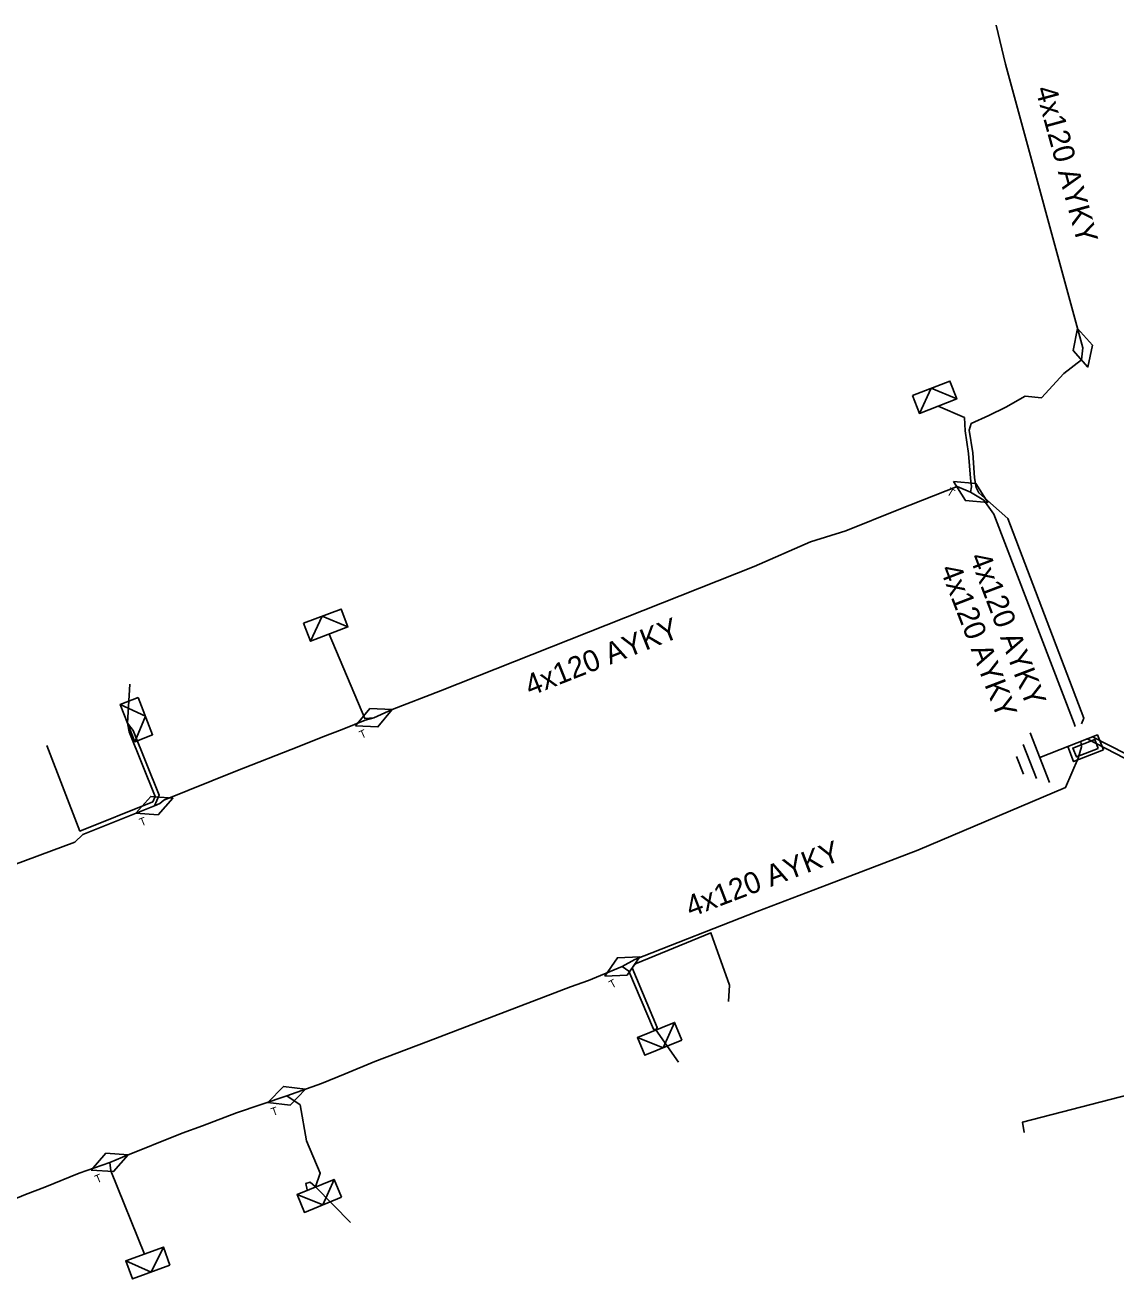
# Model space of a CAD drawing. Extents: x -540028 to -538776, y -1157064 to -1155670.
# Drawn here: x -539783.3 to -539732.2, y -1155842.1 to -1155783.4 of the extents above; entities that cross this region are included whole.
import ezdxf

# ---------------------------------------------------------------- set-up
doc = ezdxf.new("R2010")
doc.units = 0
for name, color, linetype in [('Vrstva 15', 7, 'Continuous'), ('Vrstva 19', 7, 'Continuous'), ('Vrstva 2', 7, 'Continuous'), ('Vrstva 28', 7, 'Continuous'), ('Vrstva 31', 7, 'Continuous'), ('Vrstva 5', 7, 'Continuous'), ('Vrstva 52', 7, 'Continuous'), ('Vrstva 59', 7, 'Continuous'), ('Vrstva 6', 7, 'Continuous')]:
    doc.layers.add(name, color=color, linetype=linetype)

# ---------------------------------------------------------------- blocks, each defined once
blk = doc.blocks.new('17')
at = {"layer": 'Vrstva 2'}
blk.add_lwpolyline([(-1.875, 0), (0, 0.9375), (1.875, 0), (0, -0.9375)], close=True, dxfattribs=at)
blk = doc.blocks.new('17.1')
at = {"layer": 'Vrstva 2'}
blk.add_lwpolyline([(-1.875, 0), (0, 0.9375), (1.875, 0), (0, -0.9375)], close=True, dxfattribs=at)
blk.add_text('T', height=0.75, dxfattribs=at).set_placement((-1.875, -1.35))
blk = doc.blocks.new('132')
at = {"layer": 'Vrstva 2'}
for points in [[(-1.5, 1.5), (1.5, 1.5), (1.5, 0), (-1.5, 0)], [(-1.1, 1.2), (1.1, 1.2), (1.1, 0.3), (-1.1, 0.3)]]:
    blk.add_lwpolyline(points, close=True, dxfattribs=at)
blk = doc.blocks.new('23')
at = {"layer": 'Vrstva 2'}
blk.add_lwpolyline([(1.875, -1.8), (-1.875, -1.8), (-1.875, 0), (1.875, 0)], close=True, dxfattribs=at)
blk.add_lwpolyline([(1.875, 0), (0, -1.8), (-1.875, 0)], dxfattribs=at)
blk = doc.blocks.new('11')
at = {"layer": 'Vrstva 2'}
for p, q in [((0, -4.3), (0, -1.3)), ((-2.5, -4.3), (2.5, -4.3)), ((-1.7, -5.3), (1.7, -5.3)), ((-0.9, -6.3), (0.9, -6.3))]:
    blk.add_line(p, q, dxfattribs=at)

msp = doc.modelspace()

# ---------------------------------------------------------------- linework, layer by layer
at = {"layer": 'Vrstva 5'}
for points in [[(-539737.801, -1155783.405), (-539737.37, -1155785.24), (-539733.75, -1155798.52)], [(-539733.804, -1155816.14), (-539733.7, -1155815.87), (-539737.26, -1155806.52), (-539738.61, -1155805.32), (-539738.746, -1155805.073), (-539738.811, -1155804.609), (-539738.901, -1155803.449), (-539739.061, -1155802.375), (-539738.97, -1155802.07), (-539738.14, -1155801.69), (-539737.35, -1155801.31), (-539736.447, -1155800.787), (-539735.68, -1155800.86), (-539734.63, -1155799.72), (-539733.81, -1155799.08), (-539733.75, -1155798.52)], [(-539734.097, -1155816.258), (-539734.15, -1155816.12), (-539737.92, -1155806.31), (-539738.38, -1155805.66), (-539739, -1155805.28), (-539739.63, -1155805.02), (-539742.36, -1155806.1), (-539744.85, -1155807.09), (-539746.49, -1155807.61), (-539749.14, -1155808.77), (-539763.83, -1155814.59), (-539766.08, -1155815.47), (-539766.94, -1155815.85), (-539767.35, -1155815.96), (-539768.42, -1155816.4), (-539769.33, -1155816.74), (-539770.45, -1155817.19), (-539773.41, -1155818.36), (-539776.78, -1155819.71), (-539776.957, -1155819.865), (-539777.218, -1155819.97)], [(-539777.218, -1155819.97), (-539776.998, -1155819.48), (-539778.217, -1155816.443), (-539778.48, -1155816.1)], [(-539733.834, -1155816.96), (-539733.81, -1155817.21), (-539733.96, -1155817.75), (-539734.55, -1155819.12), (-539741.47, -1155822.06), (-539745.72, -1155823.67), (-539749, -1155824.92), (-539754.726, -1155827.177), (-539755.31, -1155827.5)], [(-539733.288, -1155816.745), (-539731.73, -1155817.543)], [(-539777.218, -1155819.97), (-539780.574, -1155821.321), (-539780.94, -1155821.68), (-539784.34, -1155822.95), (-539784.6, -1155822.83), (-539785, -1155822.93), (-539786.12, -1155823.37), (-539788.17, -1155824.19), (-539789.28, -1155824.62), (-539791.3, -1155825.48), (-539791.66, -1155825.62), (-539792, -1155825.78), (-539794.27, -1155826.66), (-539797.23, -1155827.88), (-539797.924, -1155828.259)], [(-539785.64, -1155839.16), (-539783.26, -1155838.19), (-539782.35, -1155837.84), (-539780.74, -1155837.18), (-539779.31, -1155836.68), (-539778.71, -1155836.43), (-539775.92, -1155835.31), (-539774.97, -1155834.96), (-539773.38, -1155834.35), (-539771.025, -1155833.562), (-539769.39, -1155832.98), (-539768.28, -1155832.53), (-539766.9, -1155831.95), (-539764.38, -1155831), (-539757.73, -1155828.46), (-539756.89, -1155828.16), (-539755.31, -1155827.5)], [(-539755.31, -1155827.5), (-539754.996, -1155827.728), (-539753.856, -1155830.437), (-539753.733, -1155830.474)]]:
    msp.add_lwpolyline(points, dxfattribs=at)
at = {"layer": 'Vrstva 52'}
for points in [[(-539739, -1155805.28), (-539738.954, -1155805.027), (-539739.009, -1155804.631), (-539739.099, -1155803.471), (-539739.259, -1155802.405), (-539739.29, -1155801.79), (-539740.521, -1155801.256)], [(-539766.94, -1155815.85), (-539767.371, -1155815.884), (-539769.037, -1155811.935)], [(-539778.48, -1155816.1), (-539778.403, -1155816.517), (-539777.191, -1155819.539), (-539777.294, -1155819.785), (-539780.706, -1155821.159), (-539782.255, -1155817.143)], [(-539733.541, -1155816.84), (-539731.79, -1155817.737), (-539730.707, -1155817.838), (-539730.104, -1155817.946), (-539729.825, -1155818.209), (-539729.727, -1155818.36), (-539728.825, -1155822.193), (-539727.766, -1155827.381), (-539727.168, -1155830.13), (-539726.969, -1155832.316), (-539736.571, -1155834.796), (-539736.5, -1155835.282)], [(-539753.733, -1155830.474), (-539753.671, -1155830.359), (-539754.844, -1155827.572), (-539754.654, -1155827.363), (-539751.159, -1155825.92), (-539750.296, -1155828.374), (-539750.338, -1155829.143)], [(-539771.02, -1155833.56), (-539770.39, -1155833.99), (-539770.1, -1155835.67), (-539769.45, -1155837.19), (-539769.67, -1155837.83)], [(-539779.31, -1155836.68), (-539779.26, -1155837.08), (-539777.679, -1155840.97)]]:
    msp.add_lwpolyline(points, dxfattribs=at)
at = {"layer": 'Vrstva 59'}
for points in [[(-539778.479, -1155816.099), (-539778.367, -1155814.284)], [(-539753.733, -1155830.474), (-539752.678, -1155831.991)], [(-539769.67, -1155837.83), (-539769.92, -1155837.611), (-539770.124, -1155837.666), (-539770.069, -1155837.968)], [(-539769.67, -1155837.83), (-539768.035, -1155839.489)]]:
    msp.add_lwpolyline(points, dxfattribs=at)

# ---------------------------------------------------------------- block references
at = {"layer": 'Vrstva 15', "xscale": 0.49999999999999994, "yscale": 0.5000000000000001, "rotation": -68.52252775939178}
msp.add_blockref('11', (-539733.757, -1155816.928), dxfattribs=at)
at = {"layer": 'Vrstva 19'}
for name, p, xscale, yscale, rotation in [('17', (-539733.75, -1155798.52), 0.5000000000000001, 0.4999999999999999, -74.75218337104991), ('17.1', (-539739, -1155805.28), 0.5, 0.5, -31.504266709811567), ('17.1', (-539766.94, -1155815.85), 0.5, 0.5, 23.83873890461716), ('17.1', (-539777.218, -1155819.97), 0.49999999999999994, 0.5000000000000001, 21.936605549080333), ('17.1', (-539755.31, -1155827.5), 0.5, 0.5, 28.94619996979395), ('17.1', (-539771.02, -1155833.56), 0.49999999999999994, 0.5000000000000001, 19.586994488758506), ('17.1', (-539779.31, -1155836.68), 0.5000000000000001, 0.49999999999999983, 22.619863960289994)]:
    msp.add_blockref(name, p, dxfattribs=dict(at, xscale=xscale, yscale=yscale, rotation=rotation))
at = {"layer": 'Vrstva 28', "xscale": 0.49999999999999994, "yscale": 0.5000000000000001, "rotation": -158.52252775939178}
msp.add_blockref('132', (-539733.757, -1155816.928), dxfattribs=at)
at = {"layer": 'Vrstva 31'}
for p, xscale, yscale, rotation in [((-539740.52, -1155801.257), 0.5, 0.5, -158.7597388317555), ((-539769.036, -1155811.934), 0.5, 0.5, -159.09910284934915), ((-539778.479, -1155816.099), 0.5, 0.5, 111.23077498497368), ((-539753.733, -1155830.474), 0.49999999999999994, 0.5, 22.2407306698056), ((-539769.67, -1155837.83), 0.5000000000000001, 0.5, 22.227426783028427), ((-539777.679, -1155840.97), 0.49999999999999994, 0.5000000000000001, 20.059319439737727)]:
    msp.add_blockref('23', p, dxfattribs=dict(at, xscale=xscale, yscale=yscale, rotation=rotation))

# ---------------------------------------------------------------- texts
at = {"layer": 'Vrstva 6'}
for rotation, p in [(285.248, (-539735.976, -1155786.397)), (290.844, (-539739.064, -1155808.323)), (291.022, (-539740.445, -1155808.878)), (21.613, (-539759.623, -1155814.852)), (20.862, (-539752.109, -1155825.209))]:
    msp.add_text('4x120 AYKY', height=1, rotation=rotation, dxfattribs=at).set_placement(p)

doc.saveas('drawing.dxf')
